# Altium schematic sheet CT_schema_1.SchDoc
size 654 x 652 mm
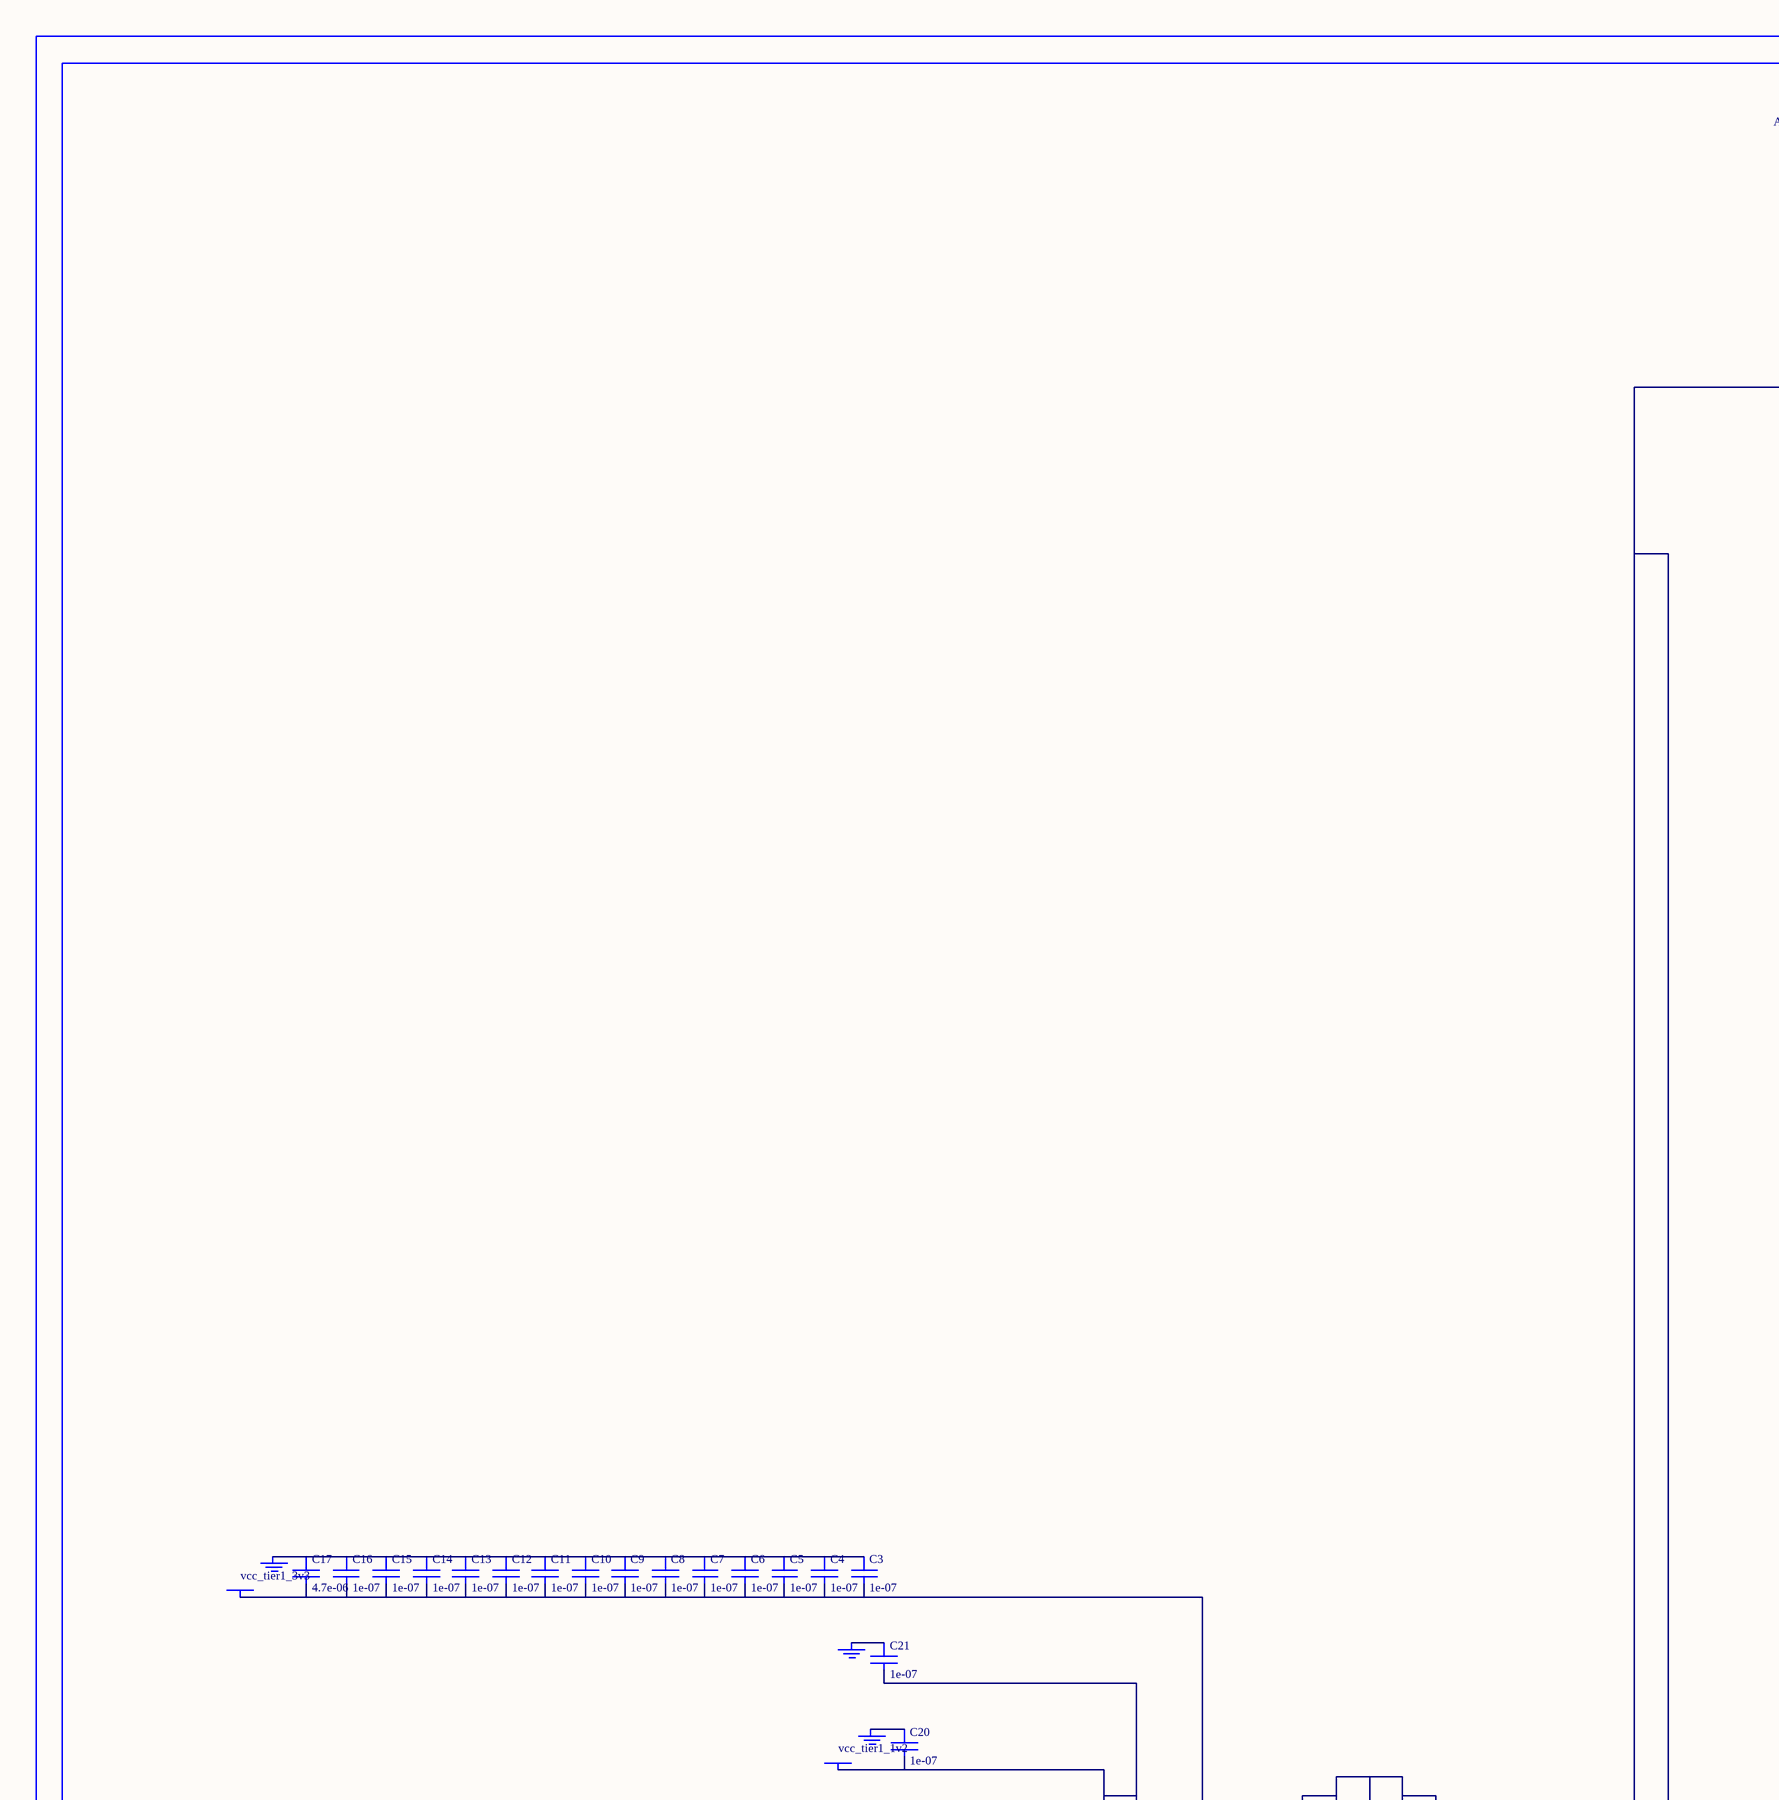
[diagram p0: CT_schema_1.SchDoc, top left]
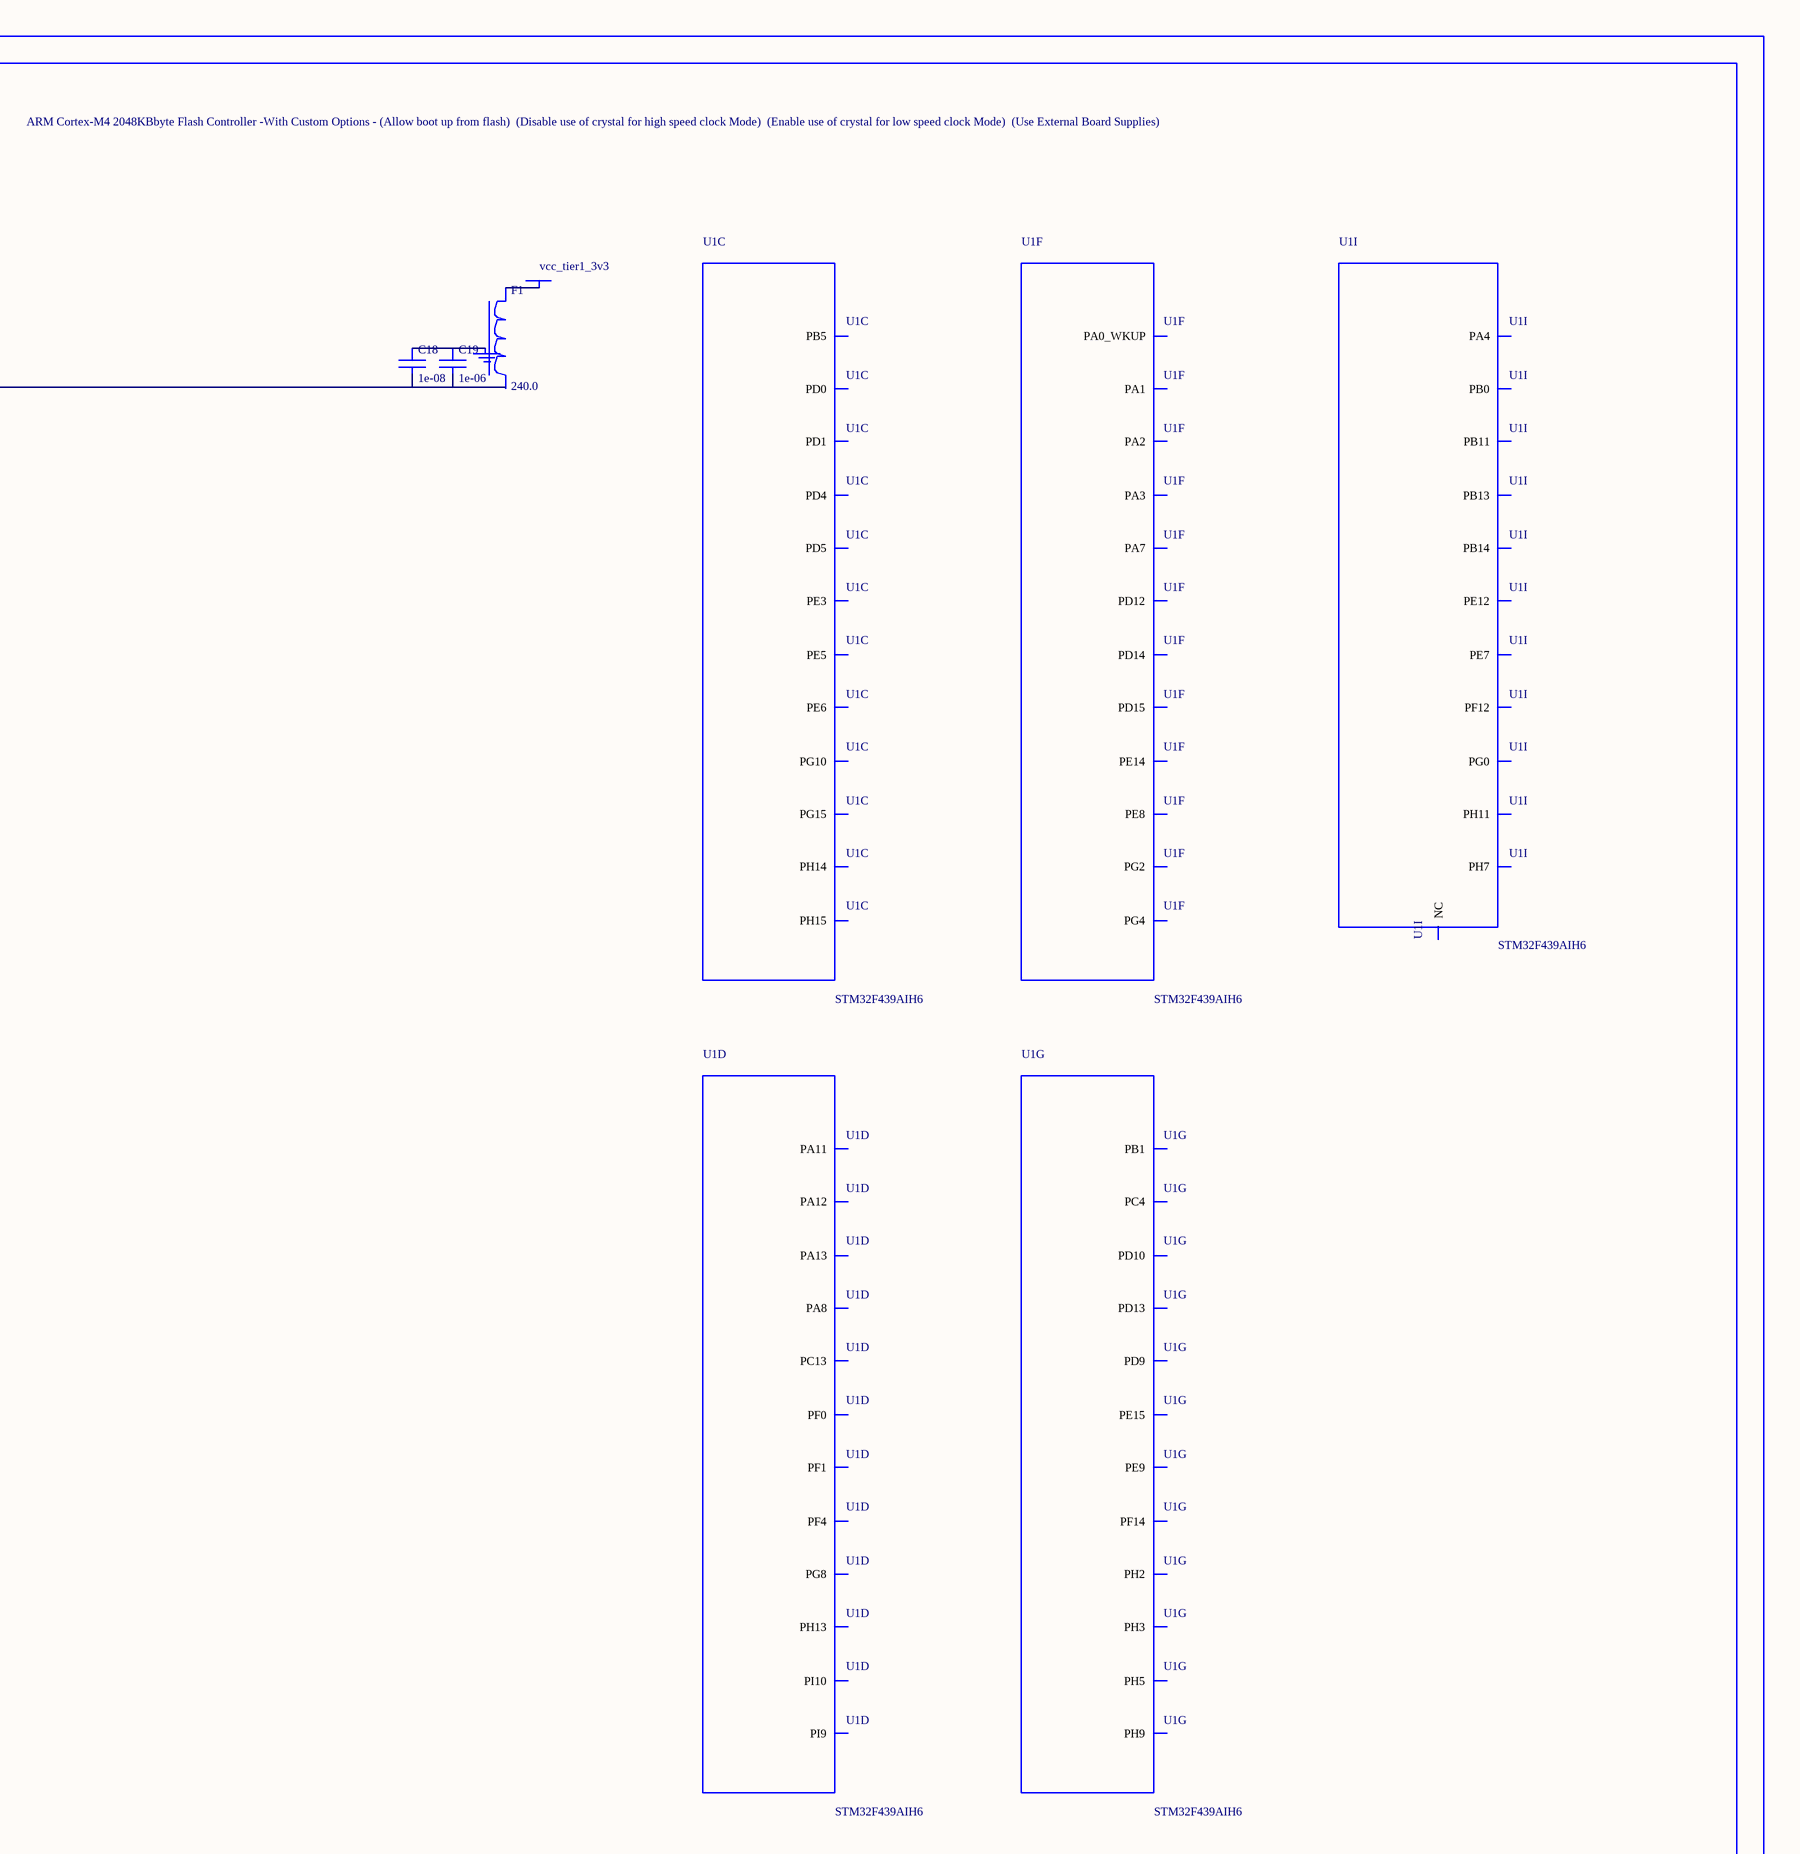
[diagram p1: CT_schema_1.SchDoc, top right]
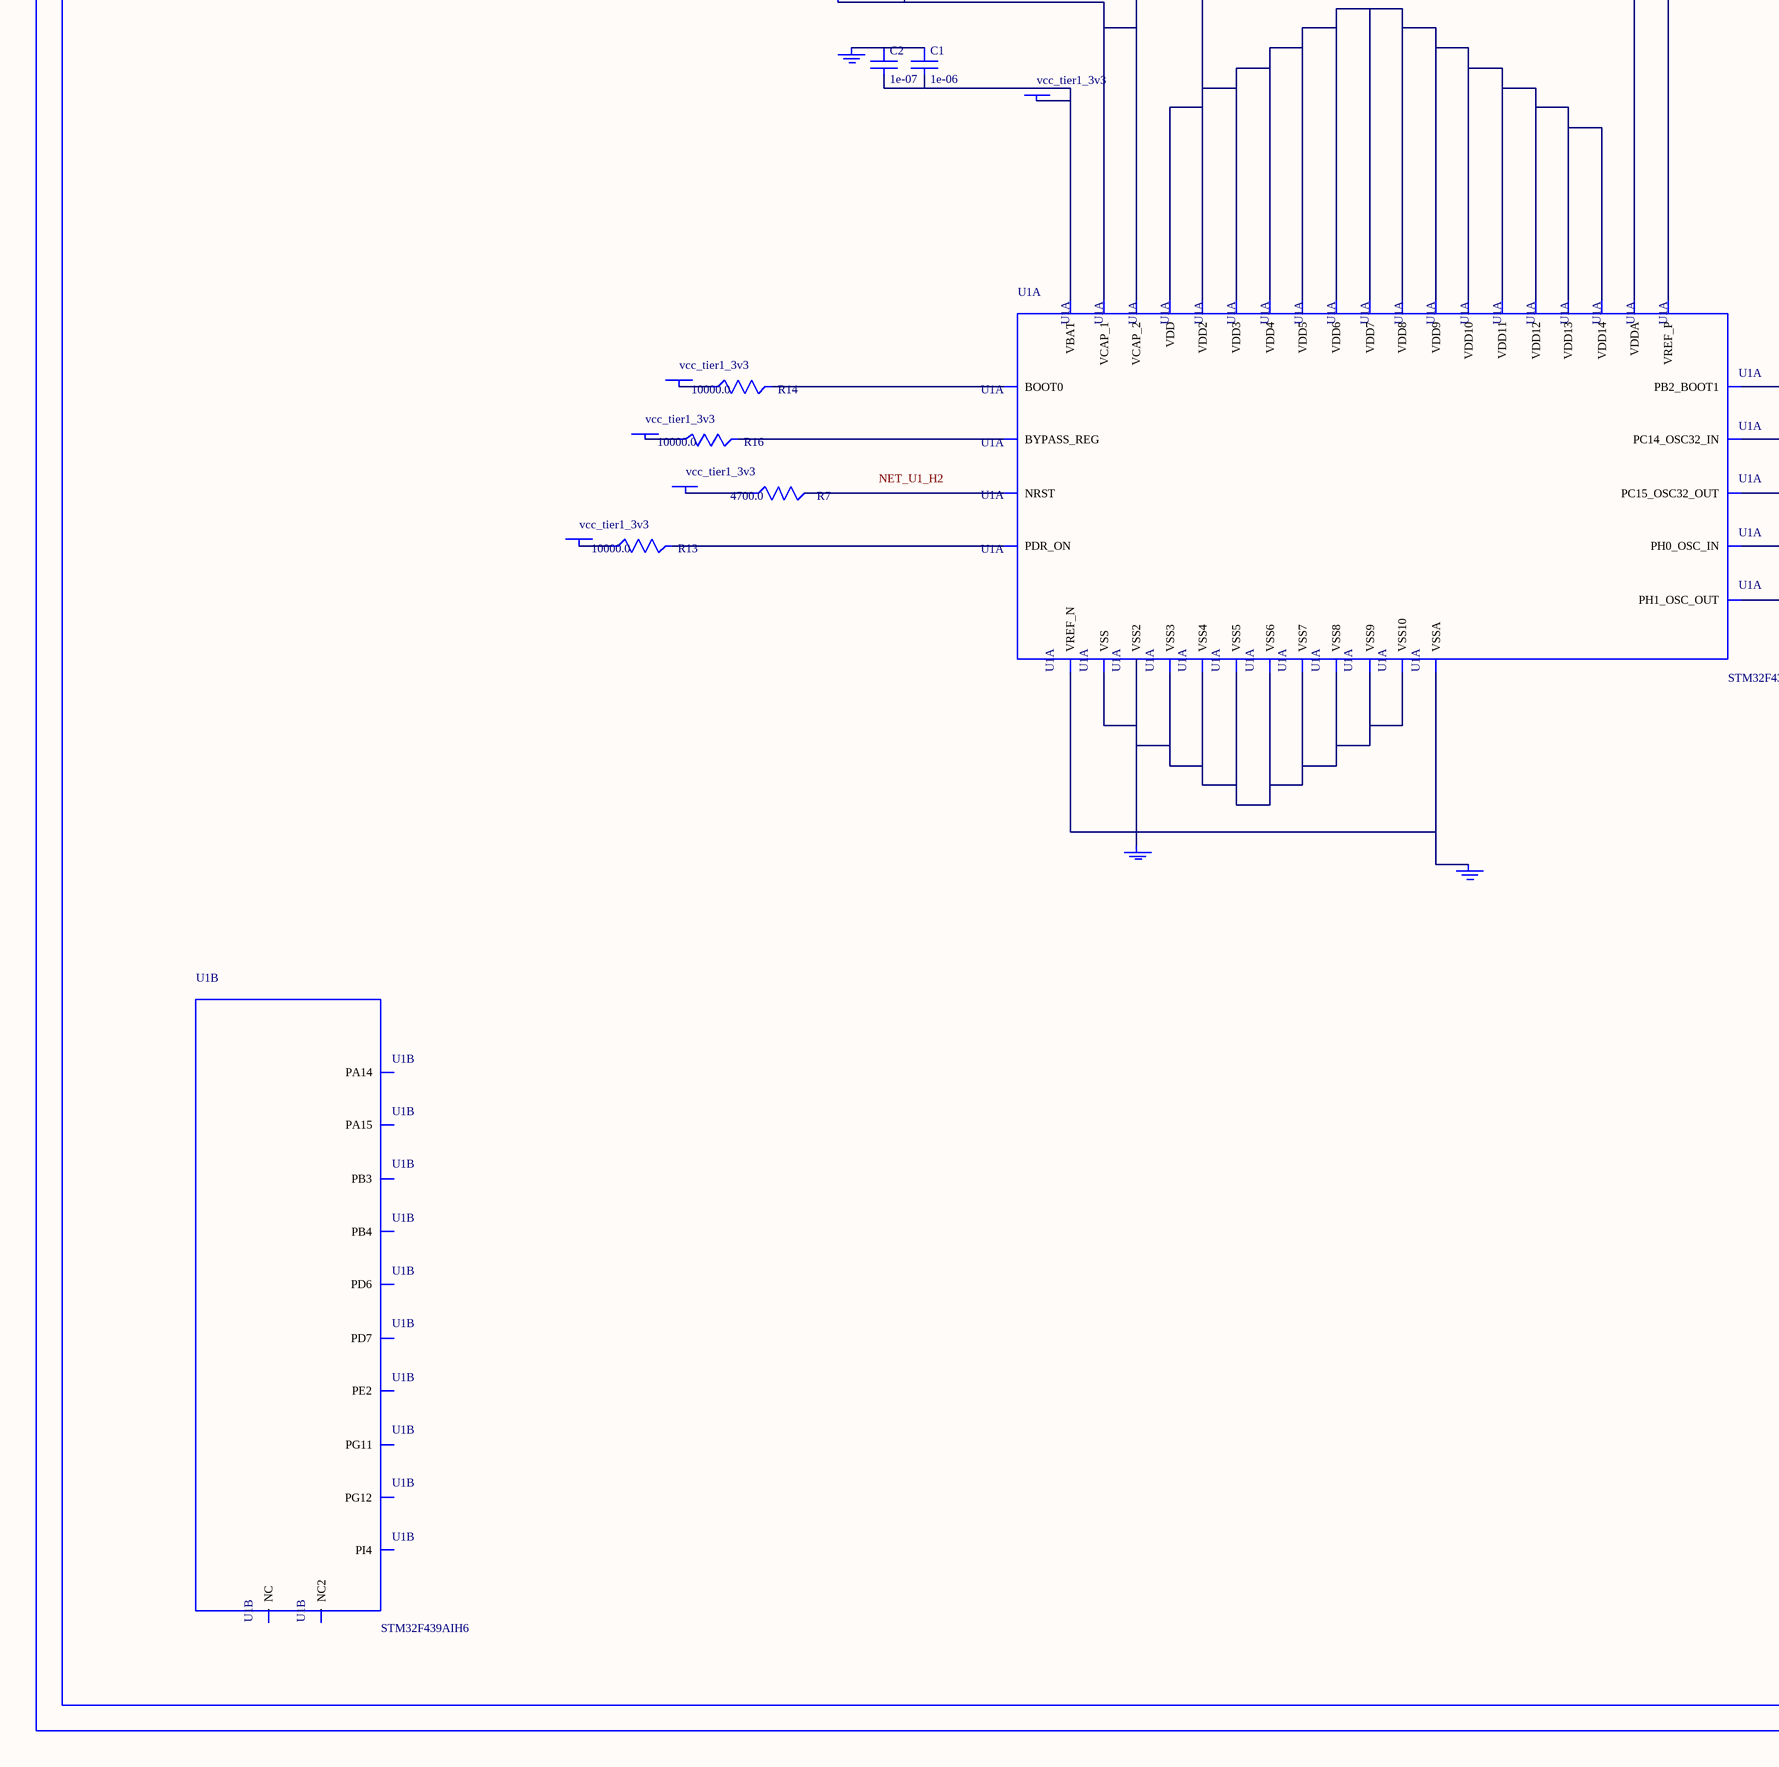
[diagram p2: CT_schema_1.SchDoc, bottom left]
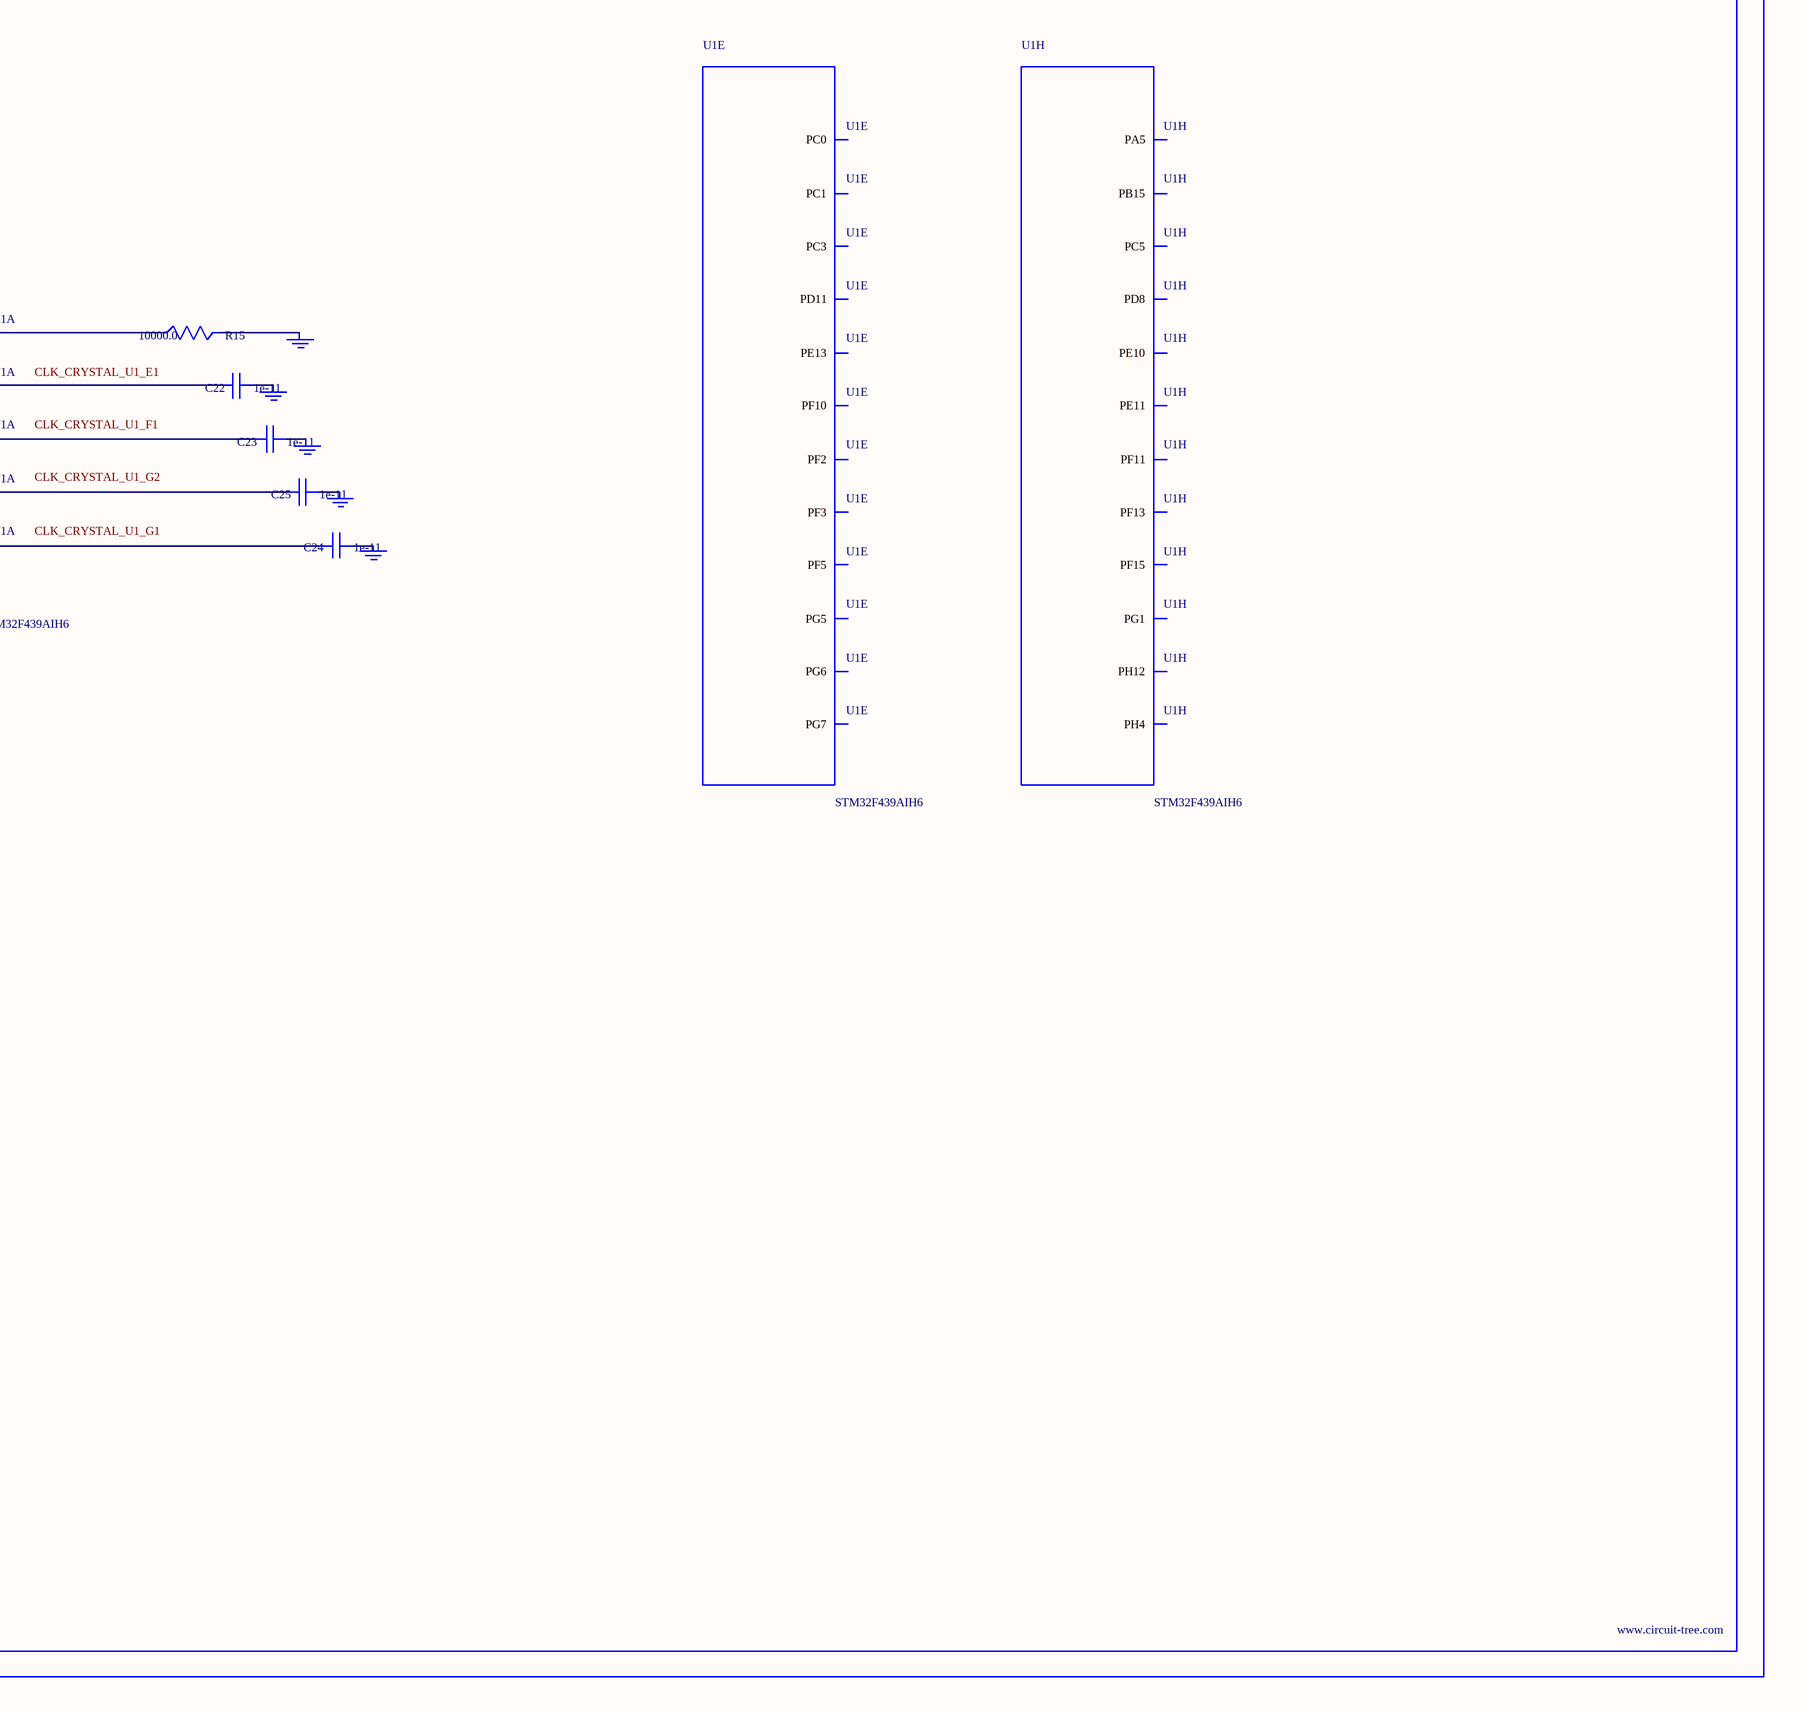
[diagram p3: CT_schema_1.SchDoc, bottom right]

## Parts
BORDER0  (no value)
C1  1e-06  [C0603]
C2  1e-07  [C0603]
C3  1e-07  [C0603]
C4  1e-07  [C0603]
C5  1e-07  [C0603]
C6  1e-07  [C0603]
C7  1e-07  [C0603]
C8  1e-07  [C0603]
C9  1e-07  [C0603]
C10  1e-07  [C0603]
C11  1e-07  [C0603]
C12  1e-07  [C0603]
C13  1e-07  [C0603]
C14  1e-07  [C0603]
C15  1e-07  [C0603]
C16  1e-07  [C0603]
C17  4.7e-06  [C0603]
C18  1e-08  [C0603]
C19  1e-06  [C0603]
C20  1e-07  [C0402]
C21  1e-07  [C0402]
C22  1e-11  [C0402]
C23  1e-11  [C0402]
C24  1e-11  [C0402]
C25  1e-11  [C0402]
F1  240.0  [L0603]
GND_INSTANCE_0_0  (no value)
GND_INSTANCE_0_1  (no value)
GND_INSTANCE_0_2  (no value)
GND_INSTANCE_0_3  (no value)
GND_INSTANCE_0_4  (no value)
GND_INSTANCE_0_5  (no value)
GND_INSTANCE_0_6  (no value)
GND_INSTANCE_0_7  (no value)
GND_INSTANCE_0_8  (no value)
GND_INSTANCE_0_9  (no value)
GND_INSTANCE_0_10  (no value)
GND_INSTANCE_0_11  (no value)
POWER_INSTANCE_0_0  vcc_tier1_3v3
POWER_INSTANCE_0_1  vcc_tier1_3v3
POWER_INSTANCE_0_2  vcc_tier1_3v3
POWER_INSTANCE_0_3  vcc_tier1_3v3
POWER_INSTANCE_0_4  vcc_tier1_3v3
POWER_INSTANCE_0_5  vcc_tier1_3v3
POWER_INSTANCE_0_6  vcc_tier1_1v2
POWER_INSTANCE_0_7  vcc_tier1_3v3
R7  4700.0  [R0603]
R13  10000.0  [R0603]
R14  10000.0  [R0603]
R15  10000.0  [R0603]
R16  10000.0  [R0603]
U1  STM32F439AIH6  [UFBGA169]  (parts A,B,C,D,E,F,G,H,I of 12)

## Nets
NetC1_1: C1.1 C2.1 GND_INSTANCE_0_0.0(GND)
NetC1_2: C1.2 C2.2 POWER_INSTANCE_0_0.0(PWR) U1.E5(VBAT)
NetC3_1: C3.1 C4.1 C5.1 C6.1 C7.1 C8.1 C9.1 C10.1 C11.1 C12.1 C13.1 C14.1 C15.1 C16.1 C17.1 GND_INSTANCE_0_2.0(GND)
NetC3_2: C3.2 C4.2 C5.2 C6.2 C7.2 C8.2 C9.2 C10.2 C11.2 C12.2 C13.2 C14.2 C15.2 C16.2 C17.2 POWER_INSTANCE_0_2.0(PWR) U1.D3(VDD2) U1.D6(VDD3) U1.D10(VDD) U1.E6(VDD4) U1.F4(VDD5) U1.F7(VDD6) U1.F8(VDD7) U1.G8(VDD9) U1.G10(VDD8) U1.H4(VDD10) U1.H8(VDD11) U1.J11(VDD12) U1.K6(VDD13) U1.L6(VDD14)
NetC18_1: C18.1 C19.1 GND_INSTANCE_0_1.0(GND)
NetC18_2: C18.2 C19.2 U1.J3(VREF_P) U1.J4(VDDA)
NetC20_1: C20.1 GND_INSTANCE_0_4.0(GND)
NetC20_2: C20.2 C21.2 POWER_INSTANCE_0_6.0(PWR) U1.D12(VCAP_2) U1.N9(VCAP_1)
NetC21_1: C21.1 GND_INSTANCE_0_5.0(GND)
NetC22_1: C22.1 GND_INSTANCE_0_6.0(GND)
NetC22_2: C22.2 U1.E1(PC14_OSC32_IN)
NetC23_1: C23.1 GND_INSTANCE_0_7.0(GND)
NetC23_2: C23.2 U1.F1(PC15_OSC32_OUT)
NetC24_1: C24.1 GND_INSTANCE_0_8.0(GND)
NetC24_2: C24.2 U1.G1(PH1_OSC_OUT)
NetC25_1: C25.1 GND_INSTANCE_0_9.0(GND)
NetC25_2: C25.2 U1.G2(PH0_OSC_IN)
NetF1_1: F1.1 POWER_INSTANCE_0_1.0(PWR)
NetGND_INSTANCE_0_3_0: GND_INSTANCE_0_3.0(GND) R15.2
NetGND_INSTANCE_0_10_0: GND_INSTANCE_0_10.0(GND) U1.J1(VSSA) U1.J2(VREF_N)
NetGND_INSTANCE_0_11_0: GND_INSTANCE_0_11.0(GND) U1.D7(VSS2) U1.D11(VSS) U1.E7(VSS3) U1.F5(VSS4) U1.F6(VSS5) U1.G7(VSS6) U1.G9(VSS7) U1.J6(VSS9) U1.J7(VSS10) U1.J10(VSS8)
NetPOWER_INSTANCE_0_3_0: POWER_INSTANCE_0_3.0(PWR) R13.1
NetPOWER_INSTANCE_0_4_0: POWER_INSTANCE_0_4.0(PWR) R14.1
NetPOWER_INSTANCE_0_5_0: POWER_INSTANCE_0_5.0(PWR) R16.1
NetPOWER_INSTANCE_0_7_0: POWER_INSTANCE_0_7.0(PWR) R7.1
NetR7_2: R7.2 U1.H2(NRST)
NetR13_2: R13.2 U1.C3(PDR_ON)
NetR14_2: R14.2 U1.A5(BOOT0)
NetR15_1: R15.1 U1.L5(PB2_BOOT1)
NetR16_2: R16.2 U1.M1(BYPASS_REG)

Not connected (* = marked no-connect by the designer): F1 2; U1 A1(NC) A6(PB4) A7(PG12) A8(PD7) A11(PA14) A13(NC2) B2(PE2) B3(PI4) B6(PB3) B7(PG11) B8(PD6) B11(PA15) C1(PE3) C6(PG15) C7(PG10) C8(PD5) C9(PD1) C12(PH15) C13(PH14) D1(PE5) D2(PE6) D5(PB5) D8(PD4) D9(PD0) D13(PH13) E2(PI9) E3(PI10) E4(PC13) E10(PA11) E11(PA12) E12(PA13) E13(PA8) F2(PF0) F3(PF1) F13(PG8) G3(PF4) G4(PF3) G5(PF2) G6(PC0) G11(PG6) G12(PG7) G13(PG5) H1(PF10) H3(PF5) H5(PC1) H7(PC3) H9(PE13) H10(PD11) H11(PD14) H12(PG4) H13(PG2) J5(PA0_WKUP) J8(PE8) J9(PE14) J12(PD15) J13(PD12) K1(PA1) K2(PA2) K3(PA3) K4(PA7) K5(PB1) K7(PF14) K8(PE9) K9(PE15) K10(PH9) K11(PD10) K12(PD13) K13(PD9) L1(PH3) L2(PH2) L3(PH5) L4(PC4) L7(PF15) L8(PE10) L11(PH12) L12(PD8) L13(PB15) M2(PH4) M3(PA5) M4(PC5) M5(PF11) M6(PF13) M7(PG1) M8(PE11) M9(PB11) M10(PH7) M11(PH11) M12(PB13) M13(PB14) N1(NC) N2(PA4) N4(PB0) N5(PF12) N6(PG0) N7(PE7) N8(PE12)

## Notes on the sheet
- Labels drawn without touching a wire or pin: CLK_CRYSTAL_U1_E1, CLK_CRYSTAL_U1_F1, CLK_CRYSTAL_U1_G1, CLK_CRYSTAL_U1_G2, NET_U1_H2

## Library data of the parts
BORDER0 = BORDER_PAGE0
C1 C19 = C0603C105K3RACTU
C2-C16 = 06035C104K4Z2A
C17 = GRM188R6YA475KE15D
C18 = 06035C103K4Z2A
C20 C21 = C0402C104K3RACTU
C22-C25 = C0402C100K3GACTU
F1 = Z0603C241ASMST
GND_INSTANCE_0_0-GND_INSTANCE_0_11 = GND
POWER_INSTANCE_0_0-POWER_INSTANCE_0_7 = PWR
R7 = RC0603JR-074K7L
R13-R16 = RC0603JR-0710KL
